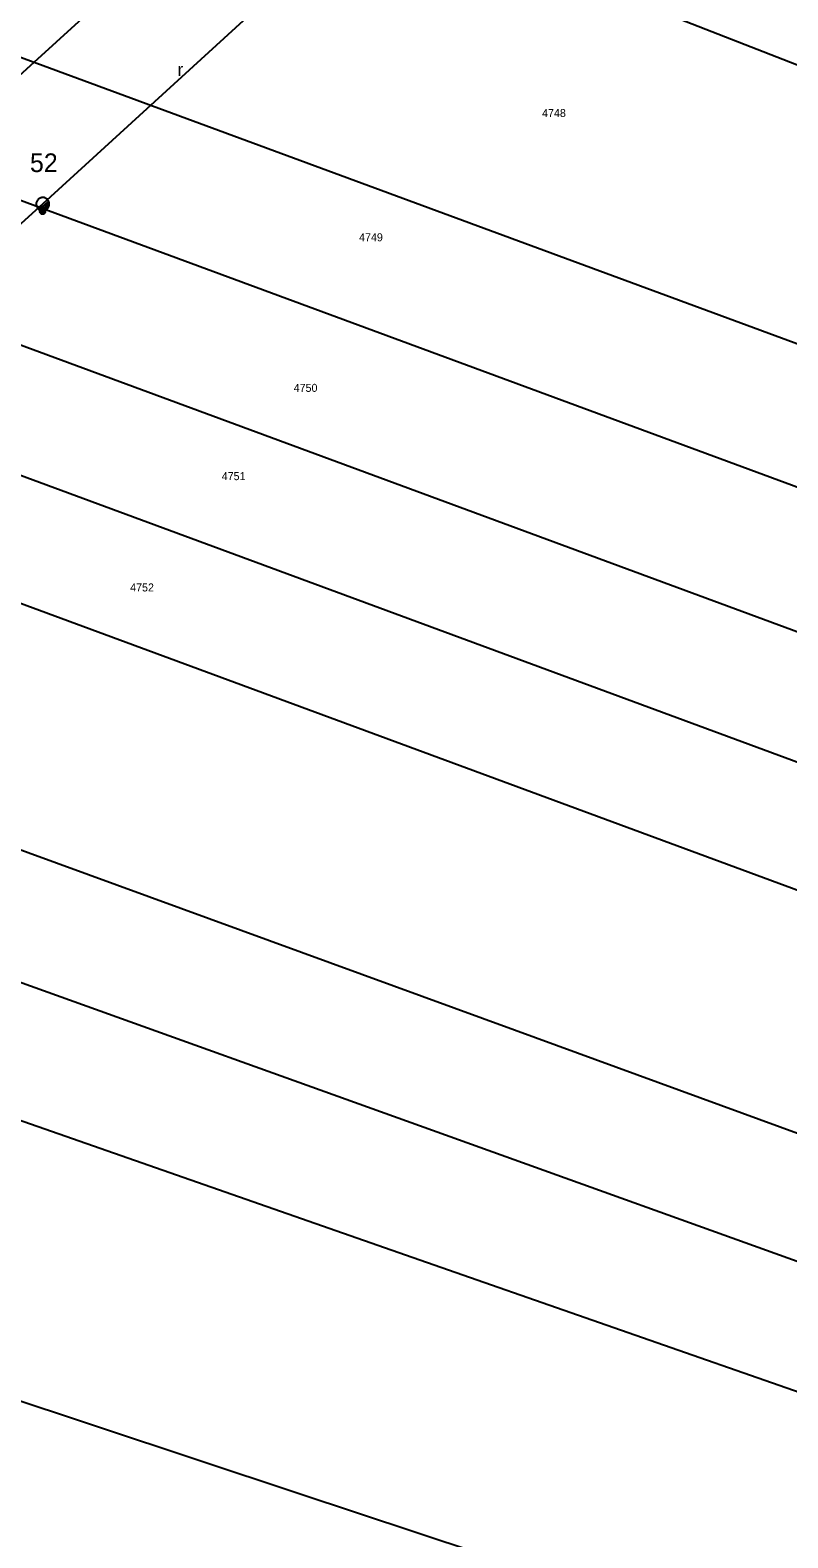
# Model space of a CAD drawing. Extents: x -540150 to -533593, y -1185082 to -1180066.
# Drawn here: x -536026.5 to -535955.3, y -1182750.7 to -1182609.1 of the extents above; entities that cross this region are included whole.
import ezdxf

# ---------------------------------------------------------------- set-up
doc = ezdxf.new("R2010")
doc.units = 0
for name, color, linetype in [('KN_HRAN_PARCEL', 7, 'Continuous'), ('KN_PARC_Č', 7, 'Continuous'), ('Vrstva 1', 7, 'Continuous'), ('Vrstva 13', 7, 'Continuous'), ('Vrstva 14', 7, 'Continuous'), ('Vrstva 2', 7, 'Continuous'), ('Vrstva 25', 7, 'Continuous'), ('Vrstva 36', 7, 'Continuous')]:
    doc.layers.add(name, color=color, linetype=linetype)

# ---------------------------------------------------------------- blocks, each defined once
blk = doc.blocks.new('VN440')
at = {"layer": 'Vrstva 2'}
for points in [[(1.22, 0), (1.21, 0.13), (1.19, 0.25), (1.16, 0.38), (1.11, 0.5), (1.05, 0.61), (0.98, 0.72), (0.9, 0.82), (0.81, 0.91), (0.71, 0.99), (0.6, 1.06), (0.49, 1.12), (0.37, 1.16), (0.25, 1.2), (0.12, 1.22), (-0.01, 1.22), (-0.14, 1.22), (-0.26, 1.2), (-0.39, 1.16), (-0.51, 1.12), (-0.62, 1.06), (-0.73, 0.99), (-0.83, 0.91), (-0.92, 0.82), (-1, 0.72), (-1.07, 0.61), (-1.13, 0.5), (-1.18, 0.38), (-1.21, 0.25), (-1.23, 0.13), (-1.24, 0), (-1.23, -0.13), (-1.21, -0.26), (-1.18, -0.38), (-1.13, -0.5), (-1.07, -0.62), (-1, -0.73), (-0.92, -0.83), (-0.83, -0.92), (-0.73, -1), (-0.62, -1.07), (-0.51, -1.13), (-0.39, -1.17), (-0.26, -1.2), (-0.14, -1.23), (-0.01, -1.23), (0.12, -1.23), (0.25, -1.2), (0.37, -1.17), (0.49, -1.13), (0.6, -1.07), (0.71, -1), (0.81, -0.92), (0.9, -0.83), (0.98, -0.73), (1.05, -0.62), (1.11, -0.5), (1.16, -0.38), (1.19, -0.26), (1.21, -0.13), (1.22, 0)], [(-1.24, 0), (1.22, 0)], [(-1.18, -0.34), (1.1, -0.34)], [(-1.01, -0.63), (0.97, -0.63)], [(-0.74, -0.92), (0.68, -0.92)]]:
    blk.add_lwpolyline(points, dxfattribs=at)

msp = doc.modelspace()

# ---------------------------------------------------------------- linework, layer by layer
at = {"layer": 'KN_HRAN_PARCEL'}
for p, q in [((-536024.71, -1182584.89), (-535911.04, -1182629.28)), ((-536039.33, -1182607.21), (-535920.59, -1182651.01)), ((-536046.43, -1182618.03), (-535926.27, -1182662.38)), ((-536053.58, -1182628.96), (-535931.57, -1182674)), ((-536060.02, -1182638.81), (-535935.48, -1182684.79)), ((-536066.38, -1182648.49), (-535940.53, -1182694.95)), ((-536078.7, -1182667.31), (-535980.98, -1182702.96)), ((-536085.47, -1182677.65), (-535986.24, -1182713.26)), ((-536092.72, -1182688.66), (-535991.23, -1182724.07)), ((-535980.98, -1182702.96), (-535904.79, -1182730.76)), ((-536107.54, -1182711.28), (-536001.29, -1182746.45)), ((-535986.24, -1182713.26), (-535912.43, -1182739.75)), ((-535991.23, -1182724.07), (-535920.17, -1182748.87)), ((-536001.29, -1182746.45), (-535936.37, -1182767.94))]:
    msp.add_line(p, q, dxfattribs=at)
at = {"layer": 'Vrstva 1'}
for points in [[(-535333.02, -1181707.83), (-535332.53, -1181735.45), (-535362.49, -1181817.72), (-535394.17, -1181900.49), (-535426.42, -1181985.39), (-535455.77, -1182060.9), (-535484.74, -1182136.41), (-535558.6, -1182202.84), (-535640.84, -1182277.72), (-535712.99, -1182341.23), (-535787.77, -1182409.75), (-535866.42, -1182480.66), (-535946.04, -1182553), (-536025.29, -1182625.41), (-536105.74, -1182698.42), (-536184.99, -1182770.53), (-536271.13, -1182849), (-536335.76, -1182908.24), (-536401.72, -1182968.91), (-536461.29, -1183023.6), (-536493.81, -1183052.39)], [(-536499.26, -1183043.55), (-536478.31, -1183024.87), (-536408.53, -1182960.47), (-536346.22, -1182903.25), (-536276.6, -1182839.44), (-536191.42, -1182762.09), (-536111.8, -1182689.91), (-536032.4, -1182617.8), (-535952.25, -1182544.86), (-535872.16, -1182472.66)]]:
    msp.add_lwpolyline(points, dxfattribs=at)
at = {"layer": 'Vrstva 25'}
for radius in [0.25, 0.2, 0.15, 0.1, 0.05]:
    msp.add_circle((-536025.3, -1182626.12), radius, dxfattribs=at)

# ---------------------------------------------------------------- block references
at = {"layer": 'Vrstva 13', "xscale": 0.5, "yscale": 0.5000000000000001, "rotation": 42.35714161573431}
msp.add_blockref('VN440', (-536025.29, -1182625.41), dxfattribs=at)

# ---------------------------------------------------------------- texts
at = {"layer": 'KN_PARC_Č'}
for s, p in [('4748', (-535978.39, -1182617.24)), ('4749', (-535995.58, -1182628.91)), ('4750', (-536001.72, -1182643.05)), ('4751', (-536008.48, -1182651.34)), ('4752', (-536017.08, -1182661.79))]:
    msp.add_text(s, height=0.75, dxfattribs=at).set_placement(p)
at = {"layer": 'Vrstva 14'}
msp.add_text('52', height=1.75, dxfattribs=at).set_placement((-536026.49, -1182622.41))
at = {"layer": 'Vrstva 36'}
msp.add_text('r', height=1.2, dxfattribs=at).set_placement((-536012.63, -1182613.38))

doc.saveas('drawing.dxf')
